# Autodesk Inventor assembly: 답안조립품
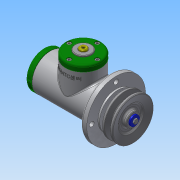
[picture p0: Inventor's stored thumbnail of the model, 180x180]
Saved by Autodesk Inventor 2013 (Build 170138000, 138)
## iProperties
Created: 2016-08
Part Number: 답안조립품
Document SubType Name: Assembly
Designer: Administrator
Author: Administrator
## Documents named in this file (25)
- C:\Users\Administrator\Desktop\460808V1006\답안조립품.iam
- C:\Users\Administrator\Desktop\460808V1006\본체.ipt
- C:\Users\Administrator\Desktop\460808V1006\사이드 커버.ipt
- 사이드 커버.ipt
- C:\Users\Administrator\Desktop\460808V1006\탑 커버.ipt
- 탑 커버.ipt
- C:\Users\Administrator\Desktop\460808V1006\탑 부시.ipt
- C:\Users\Administrator\Desktop\460808V1006\슬라이더.ipt
- C:\Users\Administrator\Desktop\460808V1006\오일 실 15 25 7.ipt
- C:\Users\Administrator\Desktop\460808V1006\베어링 15 x 35 x 11.ipt
- C:\Users\Administrator\Desktop\460808V1006\멈춤링 35x1.6.ipt
- C:\Users\Administrator\Desktop\460808V1006\부시2.ipt
- C:\Users\Administrator\Desktop\460808V1006\부시1.ipt
- C:\Users\Administrator\Desktop\460808V1006\편심축.ipt
- C:\Users\Administrator\Desktop\460808V1006\멈춤링 15 x 1.ipt
- C:\Users\Administrator\Desktop\460808V1006\V-벨트풀리.ipt
- C:\Users\Administrator\Desktop\460808V1006\키 4 x 4 x 18.ipt
- C:\Users\Administrator\Desktop\460808V1006\와셔 4x16.ipt
- C:\Users\Administrator\Desktop\460808V1006\볼트 M4 x 10.ipt
- C:\Users\Administrator\Desktop\460808V1006\와셔 10x21.ipt
- C:\Users\Administrator\Desktop\460808V1006\너트 M10.ipt
- C:\Users\Administrator\Desktop\460808V1006\링크.ipt
- C:\Users\Administrator\Desktop\460808V1006\클래스터 핀 6 x 24.ipt
- C:\Users\Administrator\Desktop\460808V1006\분할핀 1.6 x 12.ipt
- C:\Users\Administrator\Desktop\460808V1006\볼트 M4 x 12.ipt
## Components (6 placed, 3 different names)
1. V-벨트풀리:1 — 각도:2
2. ISO 4017 M4 x 10:1
3. ISO 4762 M4 x 12:1
4. ISO 4762 M4 x 12:2
5. ISO 4762 M4 x 12:3
6. ISO 4762 M4 x 12:4
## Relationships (1: Angle 1)
- 각도:2 [Angle]: V-벨트풀리:1
